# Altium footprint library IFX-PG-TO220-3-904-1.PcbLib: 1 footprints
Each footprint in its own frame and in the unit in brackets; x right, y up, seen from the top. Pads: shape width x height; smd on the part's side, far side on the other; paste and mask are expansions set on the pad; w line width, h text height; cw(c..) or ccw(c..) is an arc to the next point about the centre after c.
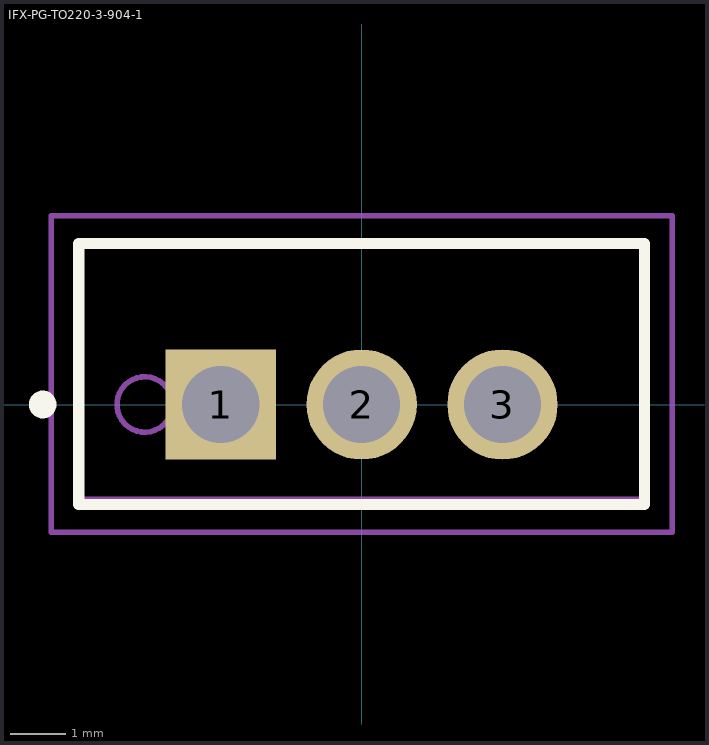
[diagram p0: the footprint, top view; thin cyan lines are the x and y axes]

## IFX-PG-TO220-3-904-1 [mm] "TO,flange mount,2.54 mm pitch, 3 pin, 10.16 mm L X 4.57 mm W X 20.56 mm H body"
height 20.56
pads (3):
  rect 1.99x1.99 hole 1.39 paste-2539.97 mask+0: 1(-2.54,0)
  round 1.99 hole 1.39 paste-2539.97 mask+0: 2(0,0) 3(2.54,0)
Top Overlay:
  circle w0.25: c-5.75,0 r0.125
  lines w0.2: -5.1,-1.8 5.1,-1.8 5.1,2.9 -5.1,2.9 -5.1,-1.8
M3 (ASY_Text_Top):
  text ".DESIGNATOR" at 0,0 h1.2
M13 (CMP_Body_OTL_Top):
  circle w0.1: c-3.912,0 r0.5
  lines w0.1: -5.08,-1.71 5.08,-1.71 5.08,2.86 -5.08,2.86 -5.08,-1.71
M15 (CMP_Courtyard_Top):
  lines w0.1: -0.5,0 0.5,0 ; 0,-0.5 0,0.5 ; -5.6,-2.3 5.6,-2.3 5.6,3.4 -5.6,3.4 -5.6,-2.3
3D body "PG-TO220-3-904_Z8B00198139_V06_3D.stp": height 19.84, standoff -10.77, extent -5.156,-1.72 5.156,2.86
